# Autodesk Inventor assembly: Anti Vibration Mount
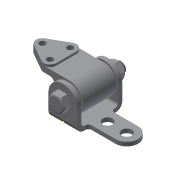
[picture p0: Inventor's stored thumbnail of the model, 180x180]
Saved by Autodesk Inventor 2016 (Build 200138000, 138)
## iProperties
Created: 2011-07
Part Number: Anti Vibration Mount
Document SubType Name: Assembly
Designer: CadCim
Author: CadCim
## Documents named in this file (5)
- D:\KAVITA\Autodesk Inventor_ 2016 Project_Kavita\Inventor_Part Files\Inventor_2016_tut\c09_Inv_tut_2016\c09_tut03_inv\Anti Vibration Mount\Anti Vibration Mount.iam
- D:\KAVITA\Autodesk Inventor_ 2016 Project_Kavita\Inventor_Part Files\Inventor_2016_tut\c09_Inv_tut_2016\c09_tut03_inv\Anti Vibration Mount\Yoke Plate.ipt
- D:\KAVITA\Autodesk Inventor_ 2016 Project_Kavita\Inventor_Part Files\Inventor_2016_tut\c09_Inv_tut_2016\c09_tut03_inv\Anti Vibration Mount\Body-Bushing Ruber.iam
- D:\KAVITA\Autodesk Inventor_ 2016 Project_Kavita\Inventor_Part Files\Inventor_2016_tut\c09_Inv_tut_2016\c09_tut03_inv\Anti Vibration Mount\Hex Bolt.ipt
- D:\KAVITA\Autodesk Inventor_ 2016 Project_Kavita\Inventor_Part Files\Inventor_2016_tut\c09_Inv_tut_2016\c09_tut03_inv\Anti Vibration Mount\Nut.ipt
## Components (4 placed, 4 different names)
1. Yoke Plate:1 — Insert:1, Angle:1, Insert:2, Mate:1
2. Body-Bushing Ruber:1 [sub-assembly] — Insert:1, Angle:1, Angle:2
3. Hex Bolt:1 — Insert:2, Angle:2, Mate:2
4. Nut:1 — Mate:1, Mate:2
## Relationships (6: Insert 2, Angle 2, Mate 2)
- Insert:1: Yoke Plate:1 ↔ Body-Bushing Ruber:1
- Angle:1: Yoke Plate:1 ↔ Body-Bushing Ruber:1
- Insert:2: Yoke Plate:1 ↔ Hex Bolt:1
- Angle:2: Body-Bushing Ruber:1 ↔ Hex Bolt:1
- Mate:1: Yoke Plate:1 ↔ Nut:1
- Mate:2: Hex Bolt:1 ↔ Nut:1
